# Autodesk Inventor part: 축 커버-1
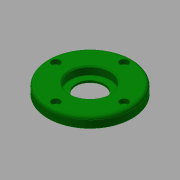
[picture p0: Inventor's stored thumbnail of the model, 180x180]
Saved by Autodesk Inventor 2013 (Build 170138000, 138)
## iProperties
Created: 2015-10
Part Number: 축 커버-1
Document SubType Name: Modeling
Designer: mdu
Density: 1 g/cm^3
Material: 강철, 연강
Author: mdu
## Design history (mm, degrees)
sketch "스케치1"
  geometry: C1 r 40 at (0, 0) reference; C2 r 26 at (0, 0) reference; 1 further point
  node "참조1"
  node "참조2"
extrude "돌출1" new body sketch "스케치1" distance "d0" = 10; taper "d1" = 0 deg
extrude "돌출2" join sketch "스케치1" distance "d2" = 3; taper "d3" = 0 deg
hole "구멍1" diameter "d6" = 27; stored, may be unused: countersink angle "d10" = 90 deg, drill point angle "d12" = 118 deg; dims "d4" = 10, "d5" = 10, "d7" = 6, "d8" = 38, "d9" = 8, "d11" = 8
sketch "스케치2"
  geometry: C1 r 20 at (0, 0); 1 further point
  constraints: 1 centre point, 1 coincident
  dimensions: "d13" = 40 diameter of C1
extrude "돌출3" cut sketch "스케치2" distance "d14" = 3; taper "d15" = 0 deg
sketch "스케치3"
  geometry: C1 r 1.621 at (0, 32.5) reference; 1 further point
hole "구멍2" sketch "스케치3" at (0, 32.5) diameter "d16" = 4.5; stored, may be unused: countersink angle "d20" = 90 deg, drill point angle "d22" = 118 deg; dims "d17" = 6, "d18" = 8, "d19" = 4.4, "d21" = 8
fillet "모깎기1" dims "d26" = 3, "d27" = 0.3
chamfer "모따기1" distance "d28" = 1; stored, may be unused: second distance "d29" = 2, angle "d30" = 45 deg
node "솔리드1"
pattern_circular "원형 패턴1" dims angle "d24" = 360 deg
node "참조3"
